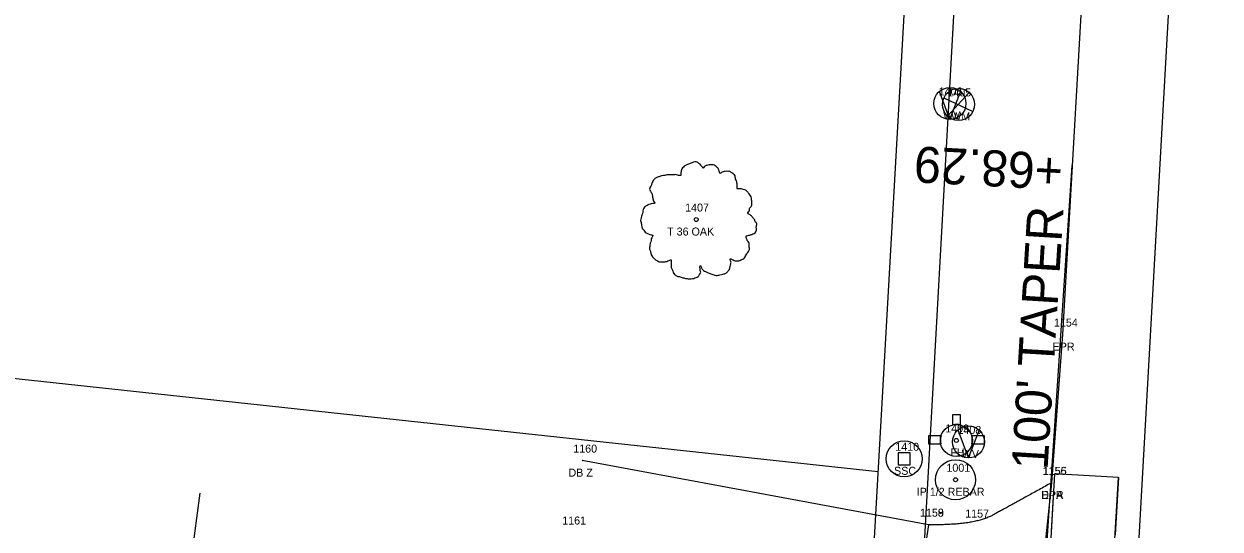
# Model space of a CAD drawing. Extents: x 1812113 to 1819860, y 1177290 to 1181185.
# Drawn here: x 1813531.1 to 1813680.6, y 1178876.4 to 1178939.4 of the extents above; entities that cross this region are included whole.
import ezdxf

# ---------------------------------------------------------------- set-up
doc = ezdxf.new("R2010")
doc.units = 0
for name, color, linetype in [('RD_EX_Driveway', 7, 'Continuous'), ('RD_EX_Driveway_txCode', 7, 'Continuous'), ('RD_EX_DV_Prop', 7, 'Continuous'), ('RD_EX_DV_Prop_txCode', 7, 'Continuous'), ('RD_EX_DV_PropPin', 7, 'Continuous'), ('RD_EX_Road', 7, 'Continuous'), ('RD_EX_Road_txCode', 7, 'Continuous'), ('RD_EX_RW', 7, 'Continuous'), ('RD_EX_UT', 7, 'Continuous'), ('RD_EX_UT_txCode', 7, 'Continuous'), ('RD_EX_VEG', 7, 'Continuous'), ('RD_EX_VEG_txCode', 7, 'Continuous'), ('RD_HC_CL', 7, 'Continuous'), ('RD_HC_Data', 7, 'Continuous'), ('RD_PD_ALT1_TnTmp', 7, 'Continuous'), ('RD_PD_ALT1_TrvlWay', 7, 'Continuous'), ('RD_PD_CstnLmt', 7, 'Continuous'), ('RD_Sketch8', 7, 'Continuous'), ('RD_SMD_Locator', 7, 'Continuous')]:
    doc.layers.add(name, color=color, linetype=linetype)

msp = doc.modelspace()

# ---------------------------------------------------------------- linework, layer by layer
at = {"layer": 'RD_EX_Driveway'}
for q in [(1813600.91, 1178884.9), (1813642.83, 1178868.05)]:
    msp.add_line((1813644.18, 1178876.9), q, dxfattribs=at)
msp.add_open_spline([(1813659.53, 1178882.12), (1813654.68, 1178879.45), (1813649.82, 1178876.78), (1813644.18, 1178876.9)], degree=2, dxfattribs=at)
at = {"layer": 'RD_EX_DV_Prop'}
msp.add_line((1813527.37, 1178895.46), (1813637.89, 1178883.55), dxfattribs=at)
at = {"layer": 'RD_EX_DV_PropPin'}
for radius in [2.5, 0.25]:
    msp.add_circle((1813647.55, 1178882.51), radius, dxfattribs=at)
at = {"layer": 'RD_EX_Road'}
for p, q in [((1813663.63, 1178947.81), (1813660.91, 1178900.64)), ((1813660.91, 1178900.64), (1813659.53, 1178882.12)), ((1813659.53, 1178882.12), (1813657.19, 1178859.48))]:
    msp.add_line(p, q, dxfattribs=at)
at = {"layer": 'RD_EX_RW'}
msp.add_line((1813632.03, 1178780.07), (1813647.58, 1179054.5), dxfattribs=at)
at = {"layer": 'RD_EX_UT'}
for p, q in [((1813646.85, 1178927.52), (1813645.55, 1178931)), ((1813646.56, 1178927.93), (1813649.23, 1178930.83)), ((1813646.85, 1178927.52), (1813648.18, 1178930.96)), ((1813646.08, 1178930.23), (1813649.71, 1178928.51)), ((1813647.19, 1178890.64), (1813647.19, 1178889.37)), ((1813648.19, 1178890.64), (1813647.19, 1178890.64)), ((1813648.19, 1178889.34), (1813648.19, 1178890.64)), ((1813649.18, 1178885.24), (1813647.88, 1178888.72)), ((1813649.18, 1178885.24), (1813650.5, 1178888.68)), ((1813645.73, 1178887.99), (1813644.17, 1178887.99)), ((1813644.17, 1178887.99), (1813644.17, 1178886.99)), ((1813644.17, 1178886.99), (1813645.69, 1178886.99)), ((1813651.17, 1178887.99), (1813649.56, 1178887.99)), ((1813649.6, 1178886.99), (1813651.17, 1178886.99)), ((1813651.17, 1178886.99), (1813651.17, 1178887.99)), ((1813641.87, 1178885.88), (1813640.37, 1178885.88)), ((1813640.37, 1178885.88), (1813640.37, 1178884.38)), ((1813641.87, 1178884.38), (1813641.87, 1178885.88)), ((1813640.37, 1178884.38), (1813641.87, 1178884.38))]:
    msp.add_line(p, q, dxfattribs=at)
for centre, radius in [((1813646.85, 1178929.51), 2), ((1813647.92, 1178929.39), 2), ((1813647.65, 1178887.42), 2), ((1813649.18, 1178887.23), 2), ((1813641.12, 1178885.13), 2.25), ((1813647.65, 1178887.42), 0.25)]:
    msp.add_circle(centre, radius, dxfattribs=at)
for start, end in [(74.2455, 103.2128), (163.3387, 192.315), (347.685, 16.6613)]:
    msp.add_arc((1813647.65, 1178887.42), 2, start, end, dxfattribs=at)
at = {"layer": 'RD_EX_VEG'}
for centre, radius in [((1813615.14, 1178915.01), 0.25), ((1813615.13, 1178914.99), 0.0001)]:
    msp.add_circle(centre, radius, dxfattribs=at)
for points in [[(1813615.28, 1178922.18), (1813614.98, 1178922.21), (1813614.65, 1178922.11), (1813614.4, 1178922.01), (1813614.18, 1178921.93), (1813613.95, 1178921.83), (1813613.65, 1178921.66), (1813613.43, 1178921.46), (1813613.3, 1178921.21), (1813613.25, 1178920.98), (1813613.2, 1178920.71), (1813613.2, 1178920.53), (1813613.08, 1178920.51), (1813612.93, 1178920.53), (1813612.68, 1178920.61), (1813612.43, 1178920.61), (1813612.18, 1178920.61), (1813611.83, 1178920.58), (1813611.48, 1178920.58), (1813611.2, 1178920.53), (1813610.88, 1178920.48), (1813610.5, 1178920.36), (1813610.15, 1178920.23), (1813609.85, 1178919.98), (1813609.6, 1178919.51), (1813609.48, 1178919.16), (1813609.33, 1178918.91), (1813609.48, 1178918.46), (1813609.65, 1178918.11), (1813609.68, 1178917.91), (1813609.75, 1178917.48), (1813609.85, 1178917.26), (1813609.98, 1178917.06), (1813609.9, 1178917.03), (1813609.53, 1178916.98), (1813609.23, 1178916.88), (1813608.8, 1178916.66), (1813608.58, 1178916.43), (1813608.48, 1178916.11), (1813608.45, 1178915.76), (1813608.35, 1178915.56), (1813608.28, 1178915.28), (1813608.25, 1178915.21), (1813608.2, 1178914.88), (1813608.3, 1178914.43), (1813608.33, 1178914.08), (1813608.45, 1178913.86), (1813608.6, 1178913.68), (1813608.78, 1178913.43), (1813609.18, 1178913.21), (1813609.5, 1178913.11), (1813609.7, 1178913.09), (1813609.53, 1178912.59), (1813609.48, 1178912.24), (1813609.35, 1178911.84), (1813609.35, 1178911.76), (1813609.3, 1178911.29), (1813609.45, 1178910.96), (1813609.53, 1178910.59), (1813609.7, 1178910.36), (1813609.98, 1178910.06), (1813610.3, 1178909.84), (1813610.8, 1178909.71), (1813611.2, 1178909.74), (1813611.78, 1178909.91), (1813612.03, 1178909.99), (1813612, 1178909.81), (1813612.03, 1178909.44), (1813612.03, 1178909.01), (1813612.18, 1178908.69), (1813612.28, 1178908.41), (1813612.43, 1178908.16), (1813612.75, 1178907.94), (1813613.15, 1178907.86), (1813613.58, 1178907.71), (1813614.03, 1178907.64), (1813614.53, 1178907.61), (1813615.13, 1178907.76), (1813615.4, 1178907.89), (1813615.5, 1178908.06), (1813615.7, 1178908.44), (1813615.65, 1178908.66), (1813615.68, 1178909.26), (1813615.78, 1178909.09), (1813615.95, 1178908.74), (1813616.45, 1178908.44), (1813616.85, 1178908.26), (1813617.33, 1178908.11), (1813617.63, 1178908.04), (1813618.1, 1178908.11), (1813618.48, 1178908.19), (1813618.85, 1178908.31), (1813619.15, 1178908.59), (1813619.33, 1178908.86), (1813619.38, 1178909.14), (1813619.45, 1178909.51), (1813619.5, 1178909.69)], [(1813619.5, 1178909.69), (1813619.43, 1178909.86), (1813619.38, 1178910.11), (1813619.45, 1178910.09), (1813619.62, 1178910.04), (1813619.9, 1178909.91), (1813620.12, 1178909.84), (1813620.45, 1178909.86), (1813620.72, 1178909.96), (1813621.17, 1178910.24), (1813621.45, 1178910.71), (1813621.72, 1178911.11), (1813621.8, 1178911.44), (1813621.75, 1178911.66), (1813621.72, 1178912.16), (1813621.52, 1178912.41), (1813621.47, 1178912.54), (1813621.37, 1178912.94), (1813621.45, 1178912.99), (1813621.72, 1178913.04), (1813622.1, 1178913.16), (1813622.37, 1178913.28), (1813622.6, 1178913.46), (1813622.67, 1178913.68), (1813622.65, 1178914.08), (1813622.7, 1178914.48), (1813622.62, 1178914.63), (1813622.52, 1178914.78), (1813622.45, 1178914.98), (1813622.3, 1178915.13), (1813622.2, 1178915.28), (1813622.1, 1178915.38), (1813621.97, 1178915.53), (1813621.8, 1178915.66), (1813621.65, 1178915.71), (1813621.6, 1178915.86), (1813621.75, 1178916.06), (1813621.8, 1178916.16), (1813621.82, 1178916.38), (1813622.05, 1178916.73), (1813622.1, 1178917.13), (1813622.05, 1178917.56), (1813622, 1178917.83), (1813621.85, 1178918.11), (1813621.65, 1178918.36), (1813621.52, 1178918.53), (1813621.35, 1178918.66), (1813621.02, 1178918.78), (1813620.77, 1178918.83), (1813620.42, 1178918.83), (1813620.22, 1178918.88), (1813620.25, 1178918.93), (1813620.25, 1178919.08), (1813620.25, 1178919.36), (1813620.17, 1178919.81), (1813620.02, 1178920.31), (1813620.02, 1178920.33), (1813619.92, 1178920.58), (1813619.7, 1178920.78), (1813619.52, 1178920.88), (1813619.33, 1178921.01), (1813619.08, 1178921.03), (1813618.78, 1178921.03), (1813618.5, 1178920.98), (1813618.3, 1178920.88), (1813618.13, 1178920.76), (1813618.05, 1178920.91), (1813617.95, 1178921.21), (1813617.9, 1178921.36), (1813617.75, 1178921.53), (1813617.53, 1178921.73), (1813617.08, 1178921.86), (1813616.45, 1178921.78), (1813616.15, 1178921.58), (1813616, 1178921.41), (1813615.95, 1178921.53), (1813615.75, 1178921.73), (1813615.65, 1178921.91), (1813615.48, 1178922.03), (1813615.33, 1178922.13), (1813615.23, 1178922.18)]]:
    msp.add_spline(points, degree=3, dxfattribs=at)
at = {"layer": 'RD_HC_CL'}
msp.add_line((1813663.56, 1178753.12), (1813680.53, 1179052.64), dxfattribs=at)
msp.add_arc((1813766.93, 1180445.18), 1689.31, 243.58271, 262.2191, dxfattribs=at)
at = {"layer": 'RD_HC_Data'}
msp.add_line((1813538.22, 1178771.42), (1813553.17, 1178880.85), dxfattribs=at)
at = {"layer": 'RD_PD_ALT1_TrvlWay'}
msp.add_line((1813655.44, 1178821.97), (1813662.13, 1178921.75), dxfattribs=at)
at = {"layer": 'RD_PD_CstnLmt'}
msp.add_line((1813642.54, 1178854.47), (1813648.11, 1178954.31), dxfattribs=at)
at = {"layer": 'RD_Sketch8'}
for p, q in [((1813659.91, 1178883.23), (1813657.89, 1178847.49)), ((1813667.9, 1178882.78), (1813659.91, 1178883.23)), ((1813665.87, 1178847.04), (1813667.9, 1178882.78))]:
    msp.add_line(p, q, dxfattribs=at)
for points in [[(1813659.91, 1178883.23), (1813659.71, 1178879.66), (1813659.51, 1178876.08)], [(1813667.9, 1178882.78), (1813667.7, 1178879.21), (1813667.49, 1178875.63)]]:
    msp.add_lwpolyline(points, dxfattribs=at)
at = {"layer": 'RD_SMD_Locator'}
for centre in [(1813660.91, 1178900.64), (1813600.91, 1178884.9), (1813659.53, 1178882.12), (1813659.53, 1178882.12), (1813644.18, 1178876.9), (1813644.18, 1178876.9), (1813649.82, 1178876.78)]:
    msp.add_circle(centre, 0.001, dxfattribs=at)

# ---------------------------------------------------------------- texts
at = {"layer": 'RD_EX_Driveway_txCode'}
for s, p in [('1160', (1813599.78, 1178885.9)), ('1156', (1813658.44, 1178883.12)), ('DB Z', (1813599.18, 1178882.9)), ('DPA', (1813658.26, 1178880.12)), ('1158', (1813643.11, 1178877.9)), ('1159', (1813643.11, 1178877.9)), ('1157', (1813648.76, 1178877.78)), ('1161', (1813598.4, 1178876.92))]:
    msp.add_text(s, height=1, dxfattribs=at).set_placement(p)
at = {"layer": 'RD_EX_DV_Prop_txCode'}
for s, p in [('1001', (1813646.41, 1178883.51)), ('IP 1/2 REBAR', (1813642.7, 1178880.51))]:
    msp.add_text(s, height=1, dxfattribs=at).set_placement(p)
at = {"layer": 'RD_EX_Road_txCode'}
for s, p in [('1154', (1813659.85, 1178901.64)), ('EPR', (1813659.68, 1178898.64)), ('1155', (1813658.47, 1178883.12)), ('EPR', (1813658.3, 1178880.12))]:
    msp.add_text(s, height=1, dxfattribs=at).set_placement(p)
at = {"layer": 'RD_EX_UT_txCode'}
for s, p in [('1406', (1813645.44, 1178930.51)), ('1405', (1813646.53, 1178930.39)), ('WV', (1813646, 1178927.51)), ('WM', (1813647.01, 1178927.39)), ('1409', (1813646.26, 1178888.42)), ('1408', (1813647.79, 1178888.23)), ('1410', (1813640.02, 1178886.13)), ('FH', (1813646.91, 1178885.42)), ('WV', (1813648.32, 1178885.23)), ('SSC', (1813639.87, 1178883.13))]:
    msp.add_text(s, height=1, dxfattribs=at).set_placement(p)
at = {"layer": 'RD_EX_VEG_txCode'}
for s, p in [('1407', (1813613.76, 1178916.01)), ('T 36 OAK', (1813611.51, 1178913.01))]:
    msp.add_text(s, height=1, dxfattribs=at).set_placement(p)
at = {"layer": 'RD_PD_ALT1_TnTmp'}
msp.add_text('S36%%d04\'29"E', height=6, rotation=126.0747, dxfattribs=at).set_placement((1813699.95, 1178927.2))
at = {"layer": 'RD_PD_ALT1_TrvlWay'}
for s, rotation, p in [('+68.29', 177.0283, (1813661.07, 1178923.2)), ("100' TAPER", 86.4905, (1813659.04, 1178883.66))]:
    msp.add_text(s, height=4.5, rotation=rotation, dxfattribs=at).set_placement(p)

doc.saveas('drawing.dxf')
